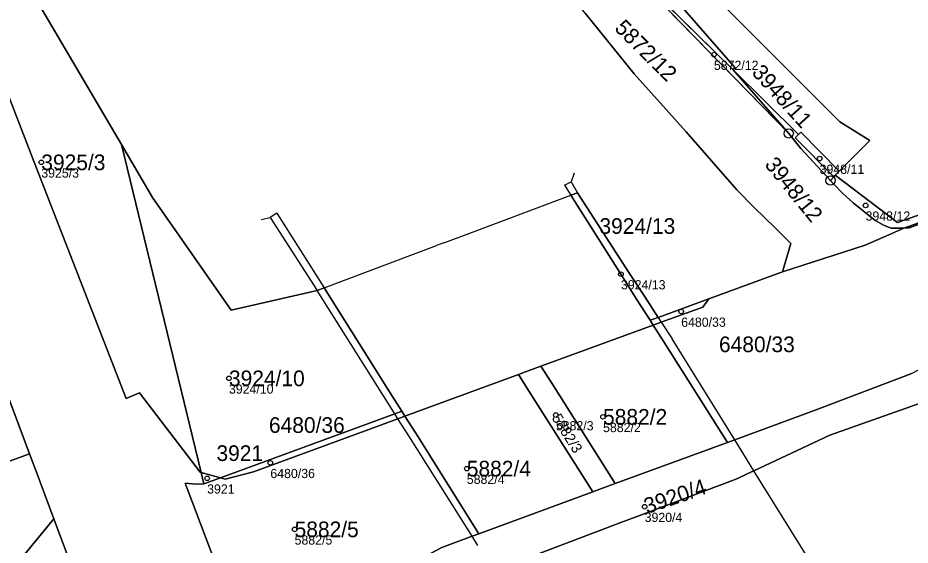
# Model space of a CAD drawing. Extents: x -690132 to -685994, y -975441 to -972444.
# Drawn here: x -688674 to -688577.2, y -974973.8 to -974916.6 of the extents above; entities that cross this region are included whole.
import ezdxf

# ---------------------------------------------------------------- set-up
doc = ezdxf.new("R2010")
doc.units = 0
for name, color, linetype in [('Definiční body', 7, 'Continuous'), ('Hranice parcel', 7, 'Continuous'), ('Parcelní čísla', 7, 'Continuous'), ('Polygon budovy', 7, 'Continuous'), ('Polygon parcely', 7, 'Continuous'), ('Vnitřní kresba', 7, 'Continuous'), ('Značky bodu BP', 7, 'Continuous')]:
    doc.layers.add(name, color=color, linetype=linetype)

msp = doc.modelspace()

# ---------------------------------------------------------------- linework, layer by layer
at = {"layer": 'Definiční body'}
for centre in [(-688598.5, -974920.59), (-688587.04, -974931.87), (-688671.42, -974932.28), (-688582.06, -974936.95), (-688608.58, -974944.41), (-688602.05, -974948.47), (-688651.08, -974955.72), (-688615.64, -974959.71), (-688610.52, -974959.9), (-688646.59, -974964.89), (-688625.29, -974965.52), (-688653.44, -974966.57), (-688606.01, -974969.65), (-688643.96, -974972.11)]:
    msp.add_circle(centre, 0.25, dxfattribs=at)
at = {"layer": 'Hranice parcel'}
for p, q in [((-688590.39, -974929.14), (-688612.59, -974906.34)), ((-688612.59, -974906.34), (-688596.44, -974922.19)), ((-688590.39, -974929.14), (-688596.44, -974922.19)), ((-688662.74, -974930.34), (-688654.1, -974965.93)), ((-688584.91, -974933.23), (-688585.35, -974933.67)), ((-688683.71, -974934.45), (-688672.7, -974963.9)), ((-688569.95, -974936.59), (-688577.93, -974939.43)), ((-688599.06, -974947.09), (-688591.08, -974944.16)), ((-688604.55, -974949.1), (-688599.06, -974947.09)), ((-688617.25, -974954.41), (-688605.09, -974949.95)), ((-688605.42, -974949.42), (-688604.55, -974949.1)), ((-688605.09, -974949.95), (-688605.42, -974949.42)), ((-688604.21, -974949.63), (-688605.09, -974949.95)), ((-688632, -974959.82), (-688619.7, -974955.31)), ((-688652.01, -974966.5), (-688633.09, -974959.56)), ((-688633.09, -974959.56), (-688632.34, -974959.29)), ((-688632.34, -974959.29), (-688632, -974959.82)), ((-688632, -974959.82), (-688632.75, -974960.1)), ((-688596.25, -974962.39), (-688597.04, -974962.68)), ((-688597.04, -974962.68), (-688609.2, -974967.15)), ((-688652.01, -974966.5), (-688654.1, -974965.93)), ((-688654.1, -974965.93), (-688653.8, -974967.16)), ((-688653.8, -974967.16), (-688652.01, -974966.5)), ((-688611.63, -974968.05), (-688623.97, -974972.58)), ((-688670.07, -974970.95), (-688677.81, -974980.33)), ((-688623.97, -974972.58), (-688624.72, -974972.86))]:
    msp.add_line(p, q, dxfattribs=at)
for points in [[(-688591.08, -974944.16), (-688590.16, -974941.08), (-688591.87, -974939.39), (-688594.12, -974937.17), (-688596.03, -974935.28), (-688601.5, -974928.96), (-688607.15, -974922.68), (-688612.47, -974916.09), (-688614.14, -974913.81), (-688617.75, -974908.97), (-688622.02, -974902.73), (-688626.15, -974896.7), (-688631.47, -974886.42), (-688646.83, -974856.75), (-688647.86, -974854.76), (-688649.1, -974852.18), (-688654.03, -974842.02), (-688667.97, -974804.7), (-688674.44, -974789.23)], [(-688584.91, -974933.23), (-688581.61, -974929.91), (-688584.85, -974927.9), (-688610.79, -974901.88), (-688613.05, -974898.35), (-688645.08, -974831.55), (-688625.66, -974812.14)], [(-688705.99, -974843.69), (-688682.05, -974897.49), (-688662.74, -974930.34)], [(-688705.99, -974843.69), (-688696.56, -974868.41), (-688676.11, -974922.24), (-688671.94, -974932.9), (-688662.23, -974957.89), (-688660.76, -974957.29), (-688654.2, -974965.9), (-688654.1, -974965.93)], [(-688634.35, -974863.73), (-688624.32, -974884.07), (-688623.41, -974885.77), (-688621.5, -974889.34), (-688621.09, -974889.93), (-688619.49, -974892.23), (-688617.88, -974894.54), (-688616.77, -974896.22), (-688615.66, -974897.91), (-688613.39, -974901.2), (-688611.04, -974904.41), (-688608.72, -974907.43), (-688607.46, -974908.98), (-688606.3, -974910.42), (-688604.95, -974911.96), (-688596.19, -974922.02), (-688596.44, -974922.19)], [(-688596.44, -974922.19), (-688589.33, -974929.27), (-688589.08, -974929.01), (-688584.91, -974933.23)], [(-688585.86, -974934.25), (-688589.09, -974930.77), (-688590.39, -974929.14)], [(-688662.74, -974930.34), (-688659.36, -974936.1), (-688650.85, -974948.33), (-688641.51, -974946.19)], [(-688585.35, -974933.67), (-688578.6, -974938.79), (-688560.84, -974932.56)], [(-688585.86, -974934.25), (-688585.5, -974933.84), (-688585.35, -974933.67)], [(-688577.93, -974939.43), (-688579.3, -974939.41), (-688580.13, -974939.1), (-688581.06, -974938.54), (-688583.41, -974936.68), (-688584.53, -974935.65), (-688585.57, -974934.57), (-688585.86, -974934.25)], [(-688605.42, -974949.42), (-688606.88, -974947.11), (-688608.52, -974944.51), (-688614.01, -974935.84), (-688613.3, -974935.57)], [(-688613.3, -974935.57), (-688607.71, -974944.22), (-688606.04, -974946.8), (-688604.55, -974949.1)], [(-688577.93, -974939.43), (-688577.34, -974939.38), (-688573.63, -974938.05), (-688569.92, -974936.68), (-688569.95, -974936.59)], [(-688591.08, -974944.16), (-688582.09, -974941.28), (-688579.53, -974940.14), (-688577.93, -974939.43)], [(-688641.51, -974946.19), (-688640.76, -974945.91), (-688635.56, -974954.17), (-688633.91, -974956.8), (-688632.34, -974959.29)], [(-688599.06, -974947.09), (-688599.72, -974947.98), (-688604.21, -974949.63)], [(-688605.09, -974949.95), (-688603.94, -974951.77), (-688597.04, -974962.68)], [(-688693.28, -974953.18), (-688689.93, -974951.91), (-688687.28, -974951), (-688686.91, -974951.99), (-688686.47, -974951.83), (-688680.82, -974966.87), (-688672.7, -974963.9)], [(-688619.7, -974955.31), (-688618.92, -974955.02), (-688617.25, -974954.41)], [(-688617.25, -974954.41), (-688616.09, -974956.25), (-688609.2, -974967.15)], [(-688619.7, -974955.31), (-688618.53, -974957.15), (-688611.63, -974968.05)], [(-688577.16, -974955.24), (-688587.51, -974959.18), (-688596.25, -974962.39)], [(-688567.75, -974955.46), (-688585.94, -974961.87), (-688594.18, -974965.74)], [(-688632.75, -974960.1), (-688648.43, -974965.85), (-688651.48, -974966.65), (-688652.01, -974966.5)], [(-688632, -974959.82), (-688630.83, -974961.68), (-688623.97, -974972.58)], [(-688672.7, -974963.9), (-688672.06, -974965.62), (-688670.07, -974970.95)], [(-688594.18, -974965.74), (-688594.89, -974966.08), (-688596.03, -974966.61), (-688606.93, -974970.74), (-688608.58, -974971.37), (-688609.35, -974971.66), (-688620.96, -974976.06), (-688621.66, -974976.24), (-688622.47, -974976.45)], [(-688646.81, -974990.93), (-688647.51, -974989.09), (-688655.6, -974967.69), (-688655.82, -974967.11), (-688654.63, -974967.21), (-688653.8, -974967.16)], [(-688609.2, -974967.15), (-688610.87, -974967.76), (-688611.63, -974968.05)], [(-688670.07, -974970.95), (-688664.5, -974985.88), (-688663.99, -974987.25), (-688655.71, -975009.76)], [(-688624.72, -974972.86), (-688628, -974974.06), (-688630.52, -974975.41), (-688635.76, -974978.22), (-688641.12, -974982.46), (-688642.68, -974984.78)]]:
    msp.add_lwpolyline(points, dxfattribs=at)
at = {"layer": 'Polygon budovy'}
msp.add_lwpolyline([(-688610.79, -974901.88), (-688584.85, -974927.9), (-688581.61, -974929.91), (-688584.91, -974933.23), (-688585.35, -974933.67), (-688578.6, -974938.79), (-688560.84, -974932.56), (-688555.71, -974930.82), (-688551.35, -974926.38), (-688553.51, -974919.51), (-688553.83, -974919.02), (-688556.41, -974916.44)], dxfattribs=at)
msp.add_lwpolyline([(-688683.99, -974934.55), (-688691.83, -974937.52), (-688691.77, -974937.67), (-688689.02, -974945.01), (-688686.98, -974950.46), (-688686.47, -974951.83), (-688680.82, -974966.87), (-688672.7, -974963.9), (-688683.71, -974934.45)], close=True, dxfattribs=at)
at = {"layer": 'Polygon parcely'}
for points in [[(-688676.11, -974922.24), (-688671.94, -974932.9), (-688662.23, -974957.89), (-688660.76, -974957.29), (-688654.2, -974965.9), (-688654.1, -974965.93), (-688662.74, -974930.34), (-688682.05, -974897.49), (-688705.99, -974843.69), (-688696.56, -974868.41)], [(-688612.59, -974906.34), (-688596.44, -974922.19), (-688596.19, -974922.02), (-688604.95, -974911.96), (-688606.3, -974910.42), (-688607.46, -974908.98), (-688608.72, -974907.43), (-688611.04, -974904.41), (-688613.39, -974901.2), (-688615.66, -974897.91), (-688616.77, -974896.22), (-688617.88, -974894.54), (-688619.49, -974892.23), (-688621.09, -974889.93), (-688621.5, -974889.34), (-688623.41, -974885.77), (-688624.32, -974884.07), (-688634.35, -974863.73), (-688623.78, -974886.07), (-688620.95, -974892.04), (-688618.47, -974897.2), (-688618.35, -974897.45), (-688614.83, -974904.03)], [(-688590.39, -974929.14), (-688596.44, -974922.19), (-688612.59, -974906.34)], [(-688585.86, -974934.25), (-688585.5, -974933.84), (-688585.35, -974933.67), (-688584.91, -974933.23), (-688589.08, -974929.01), (-688589.33, -974929.27), (-688596.44, -974922.19), (-688590.39, -974929.14), (-688589.09, -974930.77)], [(-688633.09, -974959.56), (-688632.34, -974959.29), (-688633.91, -974956.8), (-688635.56, -974954.17), (-688640.76, -974945.91), (-688641.51, -974946.19), (-688650.85, -974948.33), (-688659.36, -974936.1), (-688662.74, -974930.34), (-688654.1, -974965.93), (-688652.01, -974966.5)], [(-688560.84, -974932.56), (-688578.6, -974938.79), (-688585.35, -974933.67), (-688585.5, -974933.84), (-688585.86, -974934.25), (-688585.57, -974934.57), (-688584.53, -974935.65), (-688583.41, -974936.68), (-688581.06, -974938.54), (-688580.13, -974939.1), (-688579.3, -974939.41), (-688577.93, -974939.43), (-688569.95, -974936.59), (-688561.77, -974933.68), (-688561.34, -974933.52), (-688561.14, -974933.13)], [(-688689.93, -974951.91), (-688687.28, -974951), (-688686.91, -974951.99), (-688686.47, -974951.83), (-688680.82, -974966.87), (-688672.7, -974963.9), (-688683.71, -974934.45), (-688683.99, -974934.55), (-688691.83, -974937.52), (-688698.22, -974939.94), (-688693.28, -974953.18)], [(-688605.42, -974949.42), (-688604.55, -974949.1), (-688606.04, -974946.8), (-688607.71, -974944.22), (-688613.3, -974935.57), (-688614.01, -974935.84), (-688608.52, -974944.51), (-688606.88, -974947.11)], [(-688573.63, -974938.05), (-688569.92, -974936.68), (-688569.95, -974936.59), (-688577.93, -974939.43), (-688577.34, -974939.38)], [(-688605.42, -974949.42), (-688605.09, -974949.95), (-688604.21, -974949.63), (-688599.72, -974947.98), (-688599.06, -974947.09), (-688604.55, -974949.1)], [(-688616.09, -974956.25), (-688609.2, -974967.15), (-688597.04, -974962.68), (-688603.94, -974951.77), (-688605.09, -974949.95), (-688617.25, -974954.41)], [(-688672.7, -974963.9), (-688680.82, -974966.87), (-688686.47, -974951.83), (-688686.91, -974951.99), (-688687.28, -974951), (-688689.93, -974951.91), (-688693.28, -974953.18), (-688687.33, -974969.25), (-688685.56, -974971.31), (-688677.81, -974980.33), (-688670.07, -974970.95), (-688672.06, -974965.62)], [(-688618.53, -974957.15), (-688611.63, -974968.05), (-688610.87, -974967.76), (-688609.2, -974967.15), (-688616.09, -974956.25), (-688617.25, -974954.41), (-688618.92, -974955.02), (-688619.7, -974955.31)], [(-688630.83, -974961.68), (-688623.97, -974972.58), (-688611.63, -974968.05), (-688618.53, -974957.15), (-688619.7, -974955.31), (-688632, -974959.82)], [(-688632, -974959.82), (-688632.34, -974959.29), (-688633.09, -974959.56), (-688652.01, -974966.5), (-688651.48, -974966.65), (-688648.43, -974965.85), (-688632.75, -974960.1)], [(-688651.48, -974966.65), (-688652.01, -974966.5), (-688653.8, -974967.16), (-688654.63, -974967.21), (-688655.82, -974967.11), (-688655.6, -974967.69), (-688647.51, -974989.09), (-688646.81, -974990.93), (-688642.68, -974984.78), (-688641.12, -974982.46), (-688635.76, -974978.22), (-688630.52, -974975.41), (-688628, -974974.06), (-688624.72, -974972.86), (-688623.97, -974972.58), (-688630.83, -974961.68), (-688632, -974959.82), (-688632.75, -974960.1), (-688648.43, -974965.85)], [(-688654.1, -974965.93), (-688653.8, -974967.16), (-688652.01, -974966.5)], [(-688663.3, -975011.2), (-688662.57, -975010.33), (-688660.91, -975011.72), (-688655.71, -975009.76), (-688663.99, -974987.25), (-688664.5, -974985.88), (-688670.07, -974970.95), (-688677.81, -974980.33), (-688674.41, -974989.78), (-688673.89, -974991.22), (-688671.01, -974999.24), (-688672.08, -974999.62), (-688671.55, -975001.08), (-688669.9, -975005.7)]]:
    msp.add_lwpolyline(points, close=True, dxfattribs=at)
for points in [[(-688682.05, -974897.49), (-688662.74, -974930.34), (-688659.36, -974936.1), (-688650.85, -974948.33), (-688641.51, -974946.19), (-688640.76, -974945.91)], [(-688604.95, -974911.96), (-688596.19, -974922.02), (-688596.44, -974922.19), (-688589.33, -974929.27), (-688589.08, -974929.01), (-688584.91, -974933.23), (-688581.61, -974929.91), (-688584.85, -974927.9), (-688610.79, -974901.88)], [(-688610.79, -974901.88), (-688584.85, -974927.9), (-688581.61, -974929.91), (-688584.91, -974933.23), (-688585.35, -974933.67), (-688578.6, -974938.79), (-688560.84, -974932.56), (-688555.71, -974930.82), (-688551.35, -974926.38), (-688553.51, -974919.51), (-688553.83, -974919.02), (-688556.41, -974916.44)], [(-688612.47, -974916.09), (-688607.15, -974922.68), (-688601.5, -974928.96), (-688596.03, -974935.28), (-688594.12, -974937.17), (-688591.87, -974939.39), (-688590.16, -974941.08), (-688591.08, -974944.16), (-688582.09, -974941.28), (-688579.53, -974940.14), (-688577.93, -974939.43), (-688579.3, -974939.41), (-688580.13, -974939.1), (-688581.06, -974938.54), (-688583.41, -974936.68), (-688584.53, -974935.65), (-688585.57, -974934.57), (-688585.86, -974934.25), (-688589.09, -974930.77), (-688590.39, -974929.14), (-688612.59, -974906.34)], [(-688640.76, -974945.91), (-688635.56, -974954.17), (-688633.91, -974956.8), (-688632.34, -974959.29), (-688632, -974959.82), (-688619.7, -974955.31), (-688618.92, -974955.02), (-688617.25, -974954.41), (-688605.09, -974949.95), (-688605.42, -974949.42), (-688606.88, -974947.11), (-688608.52, -974944.51), (-688614.01, -974935.84), (-688613.3, -974935.57), (-688607.71, -974944.22), (-688606.04, -974946.8), (-688604.55, -974949.1), (-688599.06, -974947.09), (-688591.08, -974944.16), (-688590.16, -974941.08), (-688591.87, -974939.39), (-688594.12, -974937.17), (-688596.03, -974935.28), (-688601.5, -974928.96), (-688607.15, -974922.68), (-688612.47, -974916.09)], [(-688599.06, -974947.09), (-688599.72, -974947.98), (-688604.21, -974949.63), (-688605.09, -974949.95), (-688603.94, -974951.77), (-688597.04, -974962.68), (-688596.25, -974962.39), (-688587.51, -974959.18), (-688577.16, -974955.24), (-688576.1, -974954.7), (-688556.06, -974944.56), (-688543.09, -974939.82), (-688532.53, -974936.02), (-688522.2, -974932.12), (-688506.9, -974927.61), (-688503.29, -974927.7), (-688498.36, -974920.97)], [(-688636.17, -975018.58), (-688636.79, -975016.97), (-688645, -974995.63), (-688646.81, -974990.93), (-688647.51, -974989.09), (-688655.6, -974967.69), (-688655.82, -974967.11), (-688654.63, -974967.21), (-688653.8, -974967.16), (-688654.1, -974965.93), (-688654.2, -974965.9), (-688660.76, -974957.29), (-688662.23, -974957.89), (-688671.94, -974932.9), (-688676.11, -974922.24)], [(-688683.71, -974934.45), (-688672.7, -974963.9), (-688672.06, -974965.62), (-688670.07, -974970.95), (-688664.5, -974985.88), (-688663.99, -974987.25), (-688655.71, -975009.76), (-688641.88, -975046.43)], [(-688573.63, -974938.05), (-688577.34, -974939.38), (-688577.93, -974939.43), (-688579.53, -974940.14), (-688582.09, -974941.28), (-688591.08, -974944.16), (-688599.06, -974947.09)], [(-688567.75, -974955.46), (-688585.94, -974961.87), (-688594.18, -974965.74), (-688594.89, -974966.08), (-688596.03, -974966.61), (-688606.93, -974970.74), (-688608.58, -974971.37), (-688609.35, -974971.66), (-688620.96, -974976.06), (-688621.66, -974976.24), (-688622.47, -974976.45), (-688632.2, -974978.96), (-688639.15, -974981.89), (-688642.68, -974984.78), (-688644.84, -974989.41), (-688644.9, -974991.67), (-688629.32, -974988.06), (-688628.24, -974988.02), (-688622.1, -974996.14), (-688613.1, -975018.98)], [(-688577.16, -974955.24), (-688587.51, -974959.18), (-688596.25, -974962.39), (-688597.04, -974962.68), (-688609.2, -974967.15), (-688610.87, -974967.76), (-688611.63, -974968.05), (-688623.97, -974972.58), (-688624.72, -974972.86), (-688628, -974974.06)], [(-688620.96, -974976.06), (-688609.35, -974971.66), (-688608.58, -974971.37), (-688606.93, -974970.74), (-688596.03, -974966.61), (-688594.89, -974966.08), (-688594.18, -974965.74), (-688585.94, -974961.87), (-688567.75, -974955.46)]]:
    msp.add_lwpolyline(points, dxfattribs=at)
at = {"layer": 'Vnitřní kresba'}
for p, q in [((-688589.33, -974929.27), (-688589.7, -974929.62)), ((-688589.7, -974929.62), (-688585.5, -974933.84)), ((-688613.634, -974933.454), (-688613.959, -974934.4)), ((-688614.71, -974934.74), (-688613.96, -974934.4)), ((-688613.96, -974934.4), (-688613.3, -974935.57)), ((-688614.71, -974934.74), (-688614.01, -974935.84)), ((-688626.11, -974940.39), (-688614.01, -974935.84)), ((-688647.589, -974938.477), (-688646.611, -974938.27)), ((-688645.87, -974937.79), (-688646.61, -974938.27)), ((-688646.61, -974938.27), (-688641.51, -974946.19)), ((-688645.87, -974937.79), (-688640.76, -974945.91)), ((-688640.76, -974945.91), (-688628.56, -974941.31)), ((-688627.77, -974941.02), (-688628.56, -974941.31)), ((-688627.77, -974941.02), (-688626.11, -974940.39)), ((-688633.09, -974959.56), (-688641.51, -974946.19)), ((-688604.55, -974949.1), (-688604.21, -974949.63)), ((-688604.21, -974949.63), (-688603.04, -974951.44)), ((-688596.25, -974962.39), (-688603.04, -974951.44)), ((-688632.75, -974960.1), (-688633.09, -974959.56)), ((-688631.58, -974961.96), (-688632.75, -974960.1)), ((-688624.72, -974972.86), (-688631.58, -974961.96)), ((-688595.67, -974963.33), (-688596.25, -974962.39)), ((-688594.18, -974965.74), (-688595.67, -974963.33)), ((-688588.12, -974975.52), (-688594.18, -974965.74)), ((-688624.09, -974973.87), (-688624.72, -974972.86))]:
    msp.add_line(p, q, dxfattribs=at)
at = {"layer": 'Značky bodu BP'}
for centre, radius in [((-688590.39, -974929.14), 0.5), ((-688590.39, -974929.14), 0.0303), ((-688585.86, -974934.25), 0.5), ((-688585.86, -974934.25), 0.0303)]:
    msp.add_circle(centre, radius, dxfattribs=at)

# ---------------------------------------------------------------- texts
at = {"layer": 'Definiční body'}
for s, p in [('5872/12', (-688598.5, -974922.246)), ('3948/11', (-688587.04, -974933.526)), ('3925/3', (-688671.42, -974933.936)), ('3948/12', (-688582.06, -974938.606)), ('3924/13', (-688608.58, -974946.066)), ('6480/33', (-688602.05, -974950.126)), ('3924/10', (-688651.08, -974957.376)), ('5882/3', (-688615.64, -974961.366)), ('5882/2', (-688610.52, -974961.556)), ('6480/36', (-688646.59, -974966.546)), ('5882/4', (-688625.29, -974967.176)), ('3921', (-688653.44, -974968.226)), ('3920/4', (-688606.01, -974971.306)), ('5882/5', (-688643.96, -974973.766))]:
    msp.add_text(s, height=1, dxfattribs=at).set_placement(p)
at = {"layer": 'Parcelní čísla'}
for s, height, rotation, p in [('5872/12', 1.7, 315, (-688609.371, -974917.82)), ('3948/11', 1.7, 312, (-688594.477, -974922.602)), ('3948/12', 1.7, 309, (-688593.073, -974932.552)), ('5882/3', 1.139, 302, (-688616.122, -974960.011)), ('3920/4', 1.7, 19, (-688605.733, -974970.453))]:
    msp.add_text(s, height=height, rotation=rotation, dxfattribs=at).set_placement(p)
for s, p in [('3925/3', (-688671.42, -974933.13)), ('3924/13', (-688610.91, -974940.04)), ('6480/33', (-688597.95, -974952.878)), ('3924/10', (-688651.08, -974956.57)), ('5882/2', (-688610.52, -974960.75)), ('6480/36', (-688646.74, -974961.64)), ('3921', (-688652.43, -974964.69)), ('5882/4', (-688625.29, -974966.37)), ('5882/5', (-688643.96, -974972.96))]:
    msp.add_text(s, height=1.7, dxfattribs=at).set_placement(p)

doc.saveas('drawing.dxf')
